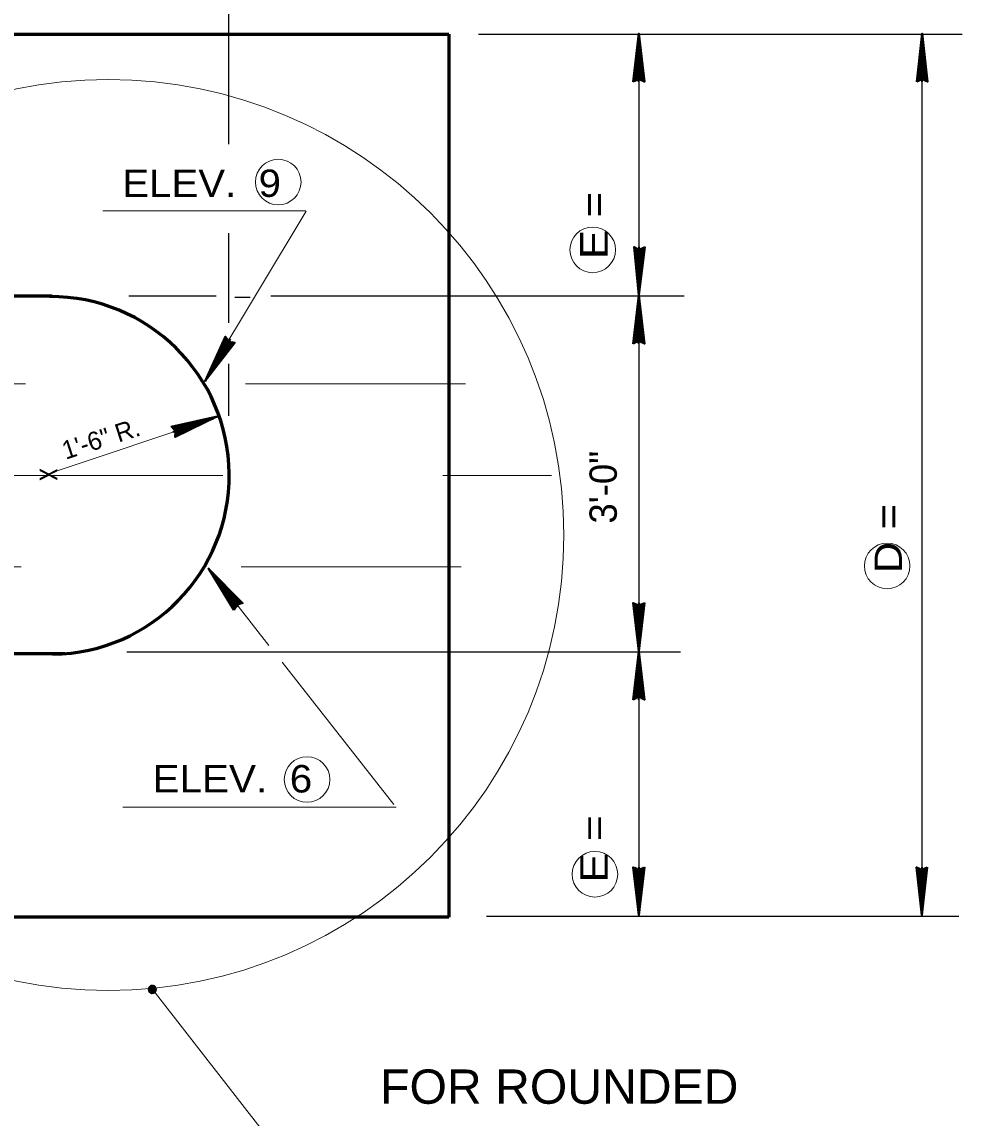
# Model space of a CAD drawing. Extents: x 1.6 to 19.9, y 2.8 to 9.5.
# Drawn here: x 17.2382 to 17.6655, y 8.7458 to 9.2441 of the extents above; entities that cross this region are included whole.
import ezdxf
from ezdxf.enums import TextEntityAlignment as Align

# ---------------------------------------------------------------- set-up
doc = ezdxf.new("R2010")
doc.units = 0
doc.header["$LTSCALE"] = 0.0047
doc.linetypes.add('DOT_DASHED', pattern=[7.7, 5, -1.2, 0.3, -1.2])
doc.layers.add('1', color=7, linetype='Continuous', lineweight=35)
doc.layers.add('5', color=7, linetype='Continuous', lineweight=13)

msp = doc.modelspace()

# ---------------------------------------------------------------- linework, layer by layer
at = {"layer": '1', "lineweight": 25}
for p, q in [((17.33225, 9.188583), (17.33225, 9.359333)), ((17.445667, 9.2385), (17.6655, 9.2385)), ((17.518583, 9.237417), (17.518583, 8.840083)), ((17.647167, 9.23825), (17.647167, 8.839)), ((17.33225, 9.107333), (17.33225, 9.148167)), ((17.28675, 9.119583), (17.3265, 9.119583)), ((17.334917, 9.119), (17.341917, 9.119)), ((17.351333, 9.119583), (17.53925, 9.119583)), ((17.33225, 9.065), (17.33225, 9.08875)), ((17.285917, 8.95775), (17.537583, 8.95775)), ((17.449333, 8.837667), (17.664083, 8.837667))]:
    msp.add_line(p, q, dxfattribs=at)
at = {"layer": '1'}
for p, q in [((17.518583, 9.216833), (17.518583, 9.238833)), ((17.647333, 9.216833), (17.647333, 9.238833)), ((17.516583, 9.21725), (17.51825, 9.233667)), ((17.516583, 9.21725), (17.518333, 9.233667)), ((17.51675, 9.21725), (17.518417, 9.233667)), ((17.645333, 9.21725), (17.647, 9.233667)), ((17.645333, 9.21725), (17.647083, 9.233667)), ((17.645333, 9.21725), (17.647167, 9.233667)), ((17.516833, 9.21725), (17.5185, 9.2335)), ((17.517, 9.21725), (17.51875, 9.2335)), ((17.519917, 9.217167), (17.518333, 9.232333)), ((17.52025, 9.21725), (17.518583, 9.232417)), ((17.520417, 9.21725), (17.51875, 9.2325)), ((17.520833, 9.21725), (17.519, 9.2325)), ((17.6455, 9.21725), (17.64725, 9.2335)), ((17.645667, 9.21725), (17.647417, 9.2335)), ((17.64875, 9.217167), (17.647083, 9.232333)), ((17.649083, 9.21725), (17.647333, 9.232417)), ((17.649333, 9.21725), (17.647667, 9.2325)), ((17.6495, 9.21725), (17.64775, 9.2325)), ((17.51675, 9.1415), (17.518333, 9.126083)), ((17.516917, 9.1415), (17.5185, 9.126083)), ((17.517167, 9.1415), (17.51875, 9.12625)), ((17.517417, 9.1415), (17.519, 9.12625)), ((17.518667, 9.141917), (17.518667, 9.119917)), ((17.520333, 9.1415), (17.518667, 9.125083)), ((17.52075, 9.1415), (17.51875, 9.125083)), ((17.521, 9.1415), (17.519, 9.125)), ((17.520917, 9.1415), (17.519, 9.125)), ((17.520833, 9.1415), (17.519, 9.125)), ((17.518583, 9.097833), (17.518583, 9.11975)), ((17.516583, 9.098333), (17.51825, 9.114667)), ((17.516583, 9.098167), (17.518333, 9.114667)), ((17.51675, 9.098167), (17.518417, 9.114667)), ((17.516833, 9.098167), (17.5185, 9.114583)), ((17.517, 9.098167), (17.51875, 9.114583)), ((17.519917, 9.098083), (17.518333, 9.113417)), ((17.52025, 9.098167), (17.518583, 9.1135)), ((17.520417, 9.098167), (17.51875, 9.113667)), ((17.520833, 9.098333), (17.519, 9.113667)), ((17.332917, 9.099917), (17.3215, 9.080833)), ((17.331, 9.100583), (17.324333, 9.086583)), ((17.331083, 9.1005), (17.324417, 9.086417)), ((17.33125, 9.100417), (17.324667, 9.086167)), ((17.3315, 9.100417), (17.325, 9.086167)), ((17.33425, 9.098667), (17.324, 9.085333)), ((17.334583, 9.098417), (17.324083, 9.085167)), ((17.334417, 9.0985), (17.32425, 9.085167)), ((17.334583, 9.098333), (17.324333, 9.085167)), ((17.334417, 9.098167), (17.324417, 9.085167)), ((17.30675, 9.057833), (17.32775, 9.065083)), ((17.306417, 9.059833), (17.323, 9.063333)), ((17.3065, 9.059833), (17.322833, 9.063333)), ((17.3065, 9.059583), (17.322833, 9.063333)), ((17.306667, 9.059833), (17.32275, 9.063583)), ((17.30675, 9.0595), (17.323, 9.06325)), ((17.30775, 9.056583), (17.321667, 9.063083)), ((17.307833, 9.056417), (17.322083, 9.063)), ((17.307833, 9.056333), (17.322, 9.06275)), ((17.308, 9.055833), (17.322, 9.062417)), ((17.336583, 8.97825), (17.323, 8.995667)), ((17.334667, 8.977167), (17.326, 8.991417)), ((17.334667, 8.977333), (17.326, 8.991333)), ((17.33475, 8.977167), (17.326083, 8.991583)), ((17.334917, 8.977333), (17.326083, 8.9915)), ((17.335083, 8.977417), (17.326333, 8.991667)), ((17.337583, 8.979417), (17.32675, 8.990417)), ((17.337667, 8.979667), (17.326833, 8.99075)), ((17.337833, 8.979833), (17.327083, 8.990917)), ((17.337917, 8.979833), (17.32725, 8.990917)), ((17.516583, 8.97975), (17.51825, 8.964417)), ((17.516833, 8.97975), (17.518417, 8.964417)), ((17.517083, 8.97975), (17.518667, 8.964417)), ((17.517333, 8.97975), (17.519, 8.9645)), ((17.518583, 8.980083), (17.518583, 8.958083)), ((17.520333, 8.97975), (17.518583, 8.963417)), ((17.520417, 8.97975), (17.518667, 8.963417)), ((17.52075, 8.97975), (17.518917, 8.963333)), ((17.520917, 8.97975), (17.519, 8.963333)), ((17.520833, 8.97975), (17.519, 8.963333)), ((17.518583, 8.936), (17.518583, 8.957917)), ((17.516583, 8.9365), (17.51825, 8.952833)), ((17.516583, 8.936333), (17.518333, 8.952833)), ((17.51675, 8.936333), (17.518417, 8.952833)), ((17.516833, 8.936333), (17.5185, 8.95275)), ((17.517, 8.936333), (17.51875, 8.95275)), ((17.519917, 8.93625), (17.518333, 8.951583)), ((17.52025, 8.936333), (17.518583, 8.951667)), ((17.520417, 8.936333), (17.51875, 8.95175)), ((17.520833, 8.9365), (17.519, 8.95175)), ((17.518583, 8.859917), (17.518583, 8.838)), ((17.647167, 8.859917), (17.647167, 8.838)), ((17.516583, 8.859583), (17.51825, 8.844333)), ((17.516833, 8.859583), (17.518417, 8.844333)), ((17.517083, 8.859583), (17.518667, 8.844417)), ((17.517333, 8.859583), (17.519, 8.8445)), ((17.520333, 8.859583), (17.518583, 8.843083)), ((17.520417, 8.859583), (17.518667, 8.843083)), ((17.52075, 8.859583), (17.518917, 8.843083)), ((17.520917, 8.859583), (17.519, 8.843083)), ((17.520833, 8.859583), (17.519, 8.843083)), ((17.645083, 8.859583), (17.646833, 8.844333)), ((17.645333, 8.859583), (17.647, 8.844333)), ((17.645583, 8.859583), (17.64725, 8.844417)), ((17.645833, 8.859583), (17.647667, 8.8445)), ((17.649, 8.859583), (17.647167, 8.843083)), ((17.649083, 8.859583), (17.64725, 8.843083)), ((17.649333, 8.859583), (17.647417, 8.843083)), ((17.649417, 8.859583), (17.647667, 8.843083)), ((17.649333, 8.859583), (17.647667, 8.843083))]:
    msp.add_line(p, q, dxfattribs=at)
at = {"layer": '1', "lineweight": 60}
for p, q in [((17.43225, 9.2385), (17.43225, 8.837167)), ((16.731, 9.119583), (17.252, 9.119583)), ((16.731, 8.957), (17.25775, 8.957)), ((17.43225, 8.837167), (16.629667, 8.837167))]:
    msp.add_line(p, q, dxfattribs=at)
at = {"layer": '1', "lineweight": 13}
for p, q in [((17.274917, 9.15825), (17.36725, 9.15825)), ((17.367417, 9.158167), (17.323583, 9.085167)), ((17.24925, 9.038417), (17.327667, 9.064583)), ((17.3505, 8.960667), (17.323583, 8.995)), ((17.407167, 8.888333), (17.356417, 8.953083)), ((17.284, 8.887167), (17.408333, 8.887167)), ((17.364083, 8.719), (17.29675, 8.805333))]:
    msp.add_line(p, q, dxfattribs=at)
at = {"layer": '1', "linetype": 'DOT_DASHED', "lineweight": 13}
for p, q in [((16.539833, 9.079667), (17.478917, 9.079667)), ((17.0295, 9.038), (17.478917, 9.038)), ((16.537917, 8.996417), (17.4745, 8.996417))]:
    msp.add_line(p, q, dxfattribs=at)
at = {"layer": '1', "lineweight": 40}
for p, q in [((17.296333, 8.805333), (17.29625, 8.803333)), ((17.2965, 8.805333), (17.296333, 8.803333)), ((17.296333, 8.805333), (17.29875, 8.80475)), ((17.296333, 8.805333), (17.29875, 8.804917)), ((17.296333, 8.805083), (17.29875, 8.804667)), ((17.2965, 8.805583), (17.29875, 8.805083)), ((17.296583, 8.805333), (17.2965, 8.803333)), ((17.296667, 8.805333), (17.296583, 8.803333)), ((17.29675, 8.805333), (17.296667, 8.803333)), ((17.297, 8.805333), (17.296917, 8.803333)), ((17.297083, 8.805333), (17.297, 8.803333)), ((17.297167, 8.805333), (17.297083, 8.803333)), ((17.29725, 8.805333), (17.297167, 8.803333)), ((17.297417, 8.805333), (17.29725, 8.803333)), ((17.2975, 8.805333), (17.297417, 8.803333)), ((17.297583, 8.805333), (17.2975, 8.803333)), ((17.29775, 8.805333), (17.297583, 8.80325)), ((17.298, 8.805333), (17.29775, 8.80325)), ((17.298083, 8.805333), (17.298, 8.80325)), ((17.298083, 8.805333), (17.298, 8.80325)), ((17.298167, 8.805333), (17.298083, 8.80325)), ((17.29825, 8.805333), (17.298167, 8.80325)), ((17.298417, 8.805333), (17.29825, 8.80325)), ((17.2985, 8.805333), (17.298417, 8.80325)), ((17.298667, 8.805333), (17.2985, 8.80325)), ((17.2985, 8.805333), (17.2985, 8.80325)), ((17.298833, 8.805333), (17.29875, 8.80325)), ((17.296167, 8.8035), (17.2985, 8.803083)), ((17.29625, 8.80475), (17.298667, 8.80425)), ((17.29625, 8.804667), (17.298667, 8.804)), ((17.29625, 8.804417), (17.2985, 8.803833)), ((17.29625, 8.804333), (17.2985, 8.803833)), ((17.29625, 8.804083), (17.2985, 8.803583)), ((17.29625, 8.803833), (17.2985, 8.803333)), ((17.29625, 8.803583), (17.2985, 8.803167)), ((17.29625, 8.803583), (17.2985, 8.80325)), ((17.296333, 8.805), (17.29875, 8.804417)), ((17.296333, 8.80475), (17.298667, 8.804333))]:
    msp.add_line(p, q, dxfattribs=at)
at = {"layer": '1'}
for points in [[(17.516083, 9.216833), (17.518583, 9.238833), (17.521167, 9.216833), (17.518583, 9.218)], [(17.645, 9.216833), (17.647333, 9.238833), (17.649833, 9.216833), (17.647333, 9.218)], [(17.52125, 9.141917), (17.518667, 9.119917), (17.516417, 9.141917), (17.51875, 9.140667)], [(17.519, 9.140333), (17.519333, 9.134), (17.519333, 9.140667), (17.5195, 9.136083), (17.51975, 9.140833), (17.51925, 9.133333), (17.51875, 9.123583), (17.518333, 9.125667), (17.518583, 9.122917), (17.5185, 9.140333), (17.518167, 9.13525), (17.518167, 9.140667), (17.519, 9.129417), (17.51775, 9.140833)], [(17.519, 9.140333), (17.519, 9.130583), (17.51875, 9.130667), (17.519, 9.1325)], [(17.516083, 9.097833), (17.518583, 9.11975), (17.521167, 9.097833), (17.518583, 9.099)], [(17.335167, 9.098417), (17.3215, 9.080833), (17.33075, 9.101083), (17.33225, 9.098833)], [(17.33225, 9.098333), (17.327417, 9.089833), (17.32725, 9.09), (17.32825, 9.091667), (17.332583, 9.098333), (17.329333, 9.092583), (17.332917, 9.098333), (17.330667, 9.094417), (17.333417, 9.098417), (17.329, 9.092167), (17.3235, 9.084), (17.324, 9.085917), (17.322833, 9.083583), (17.332, 9.0985), (17.329083, 9.094417), (17.331917, 9.099), (17.32675, 9.089083), (17.331583, 9.099417)], [(17.306083, 9.060167), (17.32775, 9.065083), (17.307833, 9.055333), (17.308, 9.058083)], [(17.334583, 8.976667), (17.323, 8.995667), (17.338583, 8.979833), (17.336, 8.979167)], [(17.521167, 8.980083), (17.518583, 8.958083), (17.516083, 8.980083), (17.518667, 8.979)], [(17.519, 8.978667), (17.519, 8.968833), (17.51875, 8.968917), (17.519, 8.97075)], [(17.516083, 8.936), (17.518583, 8.957917), (17.521167, 8.936), (17.518583, 8.93725)], [(17.521167, 8.859917), (17.518583, 8.838), (17.516083, 8.859917), (17.518667, 8.858833)], [(17.649667, 8.859917), (17.647167, 8.838), (17.644833, 8.859917), (17.64725, 8.858833)], [(17.519, 8.8585), (17.519, 8.848833), (17.51875, 8.848833), (17.519, 8.850583)], [(17.647667, 8.8585), (17.647667, 8.848833), (17.647333, 8.848833), (17.647667, 8.850583)]]:
    msp.add_lwpolyline(points, close=True, dxfattribs=at)
at = {"layer": '1', "lineweight": 60}
msp.add_lwpolyline([(16.629667, 8.837167), (16.629667, 9.2385), (17.43225, 9.2385)], dxfattribs=at)
at = {"layer": '1'}
for points in [[(17.518333, 9.218333), (17.518167, 9.228083), (17.5185, 9.228), (17.518333, 9.22625), (17.518167, 9.218333), (17.518, 9.224583), (17.517833, 9.218083), (17.51775, 9.222583), (17.5175, 9.217833), (17.518, 9.225417), (17.5185, 9.235167), (17.519, 9.233083), (17.51875, 9.235833), (17.51875, 9.218333), (17.519083, 9.223417), (17.519083, 9.218083), (17.518417, 9.229167), (17.5195, 9.217917), (17.518417, 9.218417), (17.516917, 9.217417), (17.51725, 9.217917), (17.518, 9.218417), (17.517833, 9.218833), (17.517167, 9.218583), (17.518667, 9.21825), (17.5195, 9.217833), (17.52075, 9.21725)], [(17.647083, 9.218333), (17.646917, 9.228083), (17.64725, 9.228), (17.647083, 9.22625), (17.646917, 9.218333), (17.64675, 9.224583), (17.646667, 9.218083), (17.6465, 9.222583), (17.646333, 9.217833), (17.64675, 9.225417), (17.64725, 9.235167), (17.64775, 9.233083), (17.647417, 9.235833), (17.647667, 9.218333), (17.648, 9.223417), (17.648, 9.218083), (17.647167, 9.229167), (17.648333, 9.217917), (17.647167, 9.218417), (17.645583, 9.217417), (17.645917, 9.217917), (17.64675, 9.218417), (17.646667, 9.218833), (17.645833, 9.218583), (17.647417, 9.21825), (17.648333, 9.217833), (17.649417, 9.21725)], [(17.519, 9.140333), (17.520417, 9.141333), (17.520083, 9.140833), (17.51925, 9.140333), (17.519417, 9.13975), (17.52025, 9.140167), (17.518667, 9.1405), (17.51775, 9.140917), (17.51675, 9.1415)], [(17.518333, 9.099333), (17.518167, 9.109083), (17.5185, 9.109), (17.518333, 9.107167), (17.518167, 9.099333), (17.518, 9.105667), (17.517833, 9.099083), (17.51775, 9.103667), (17.5175, 9.098833), (17.518, 9.106333), (17.5185, 9.116167), (17.519, 9.114083), (17.51875, 9.11675), (17.51875, 9.099333), (17.519083, 9.1045), (17.519083, 9.099083), (17.518417, 9.110333), (17.5195, 9.098917), (17.518417, 9.099417), (17.516917, 9.098333), (17.51725, 9.098917), (17.518, 9.099417), (17.517833, 9.099917), (17.517167, 9.099583), (17.518667, 9.099167), (17.5195, 9.098833), (17.52075, 9.098333)], [(17.33225, 9.098333), (17.33425, 9.098333), (17.333583, 9.098083), (17.332667, 9.098083), (17.3325, 9.097583), (17.333333, 9.097583), (17.332083, 9.09875), (17.331583, 9.099583), (17.330833, 9.1005)], [(17.308417, 9.058417), (17.317583, 9.061917), (17.31775, 9.06175), (17.315583, 9.061333), (17.308083, 9.05875), (17.31425, 9.061083), (17.307667, 9.058833), (17.312083, 9.060583), (17.307167, 9.059167), (17.31475, 9.061333), (17.32425, 9.063833), (17.3225, 9.06275), (17.325083, 9.063833), (17.308417, 9.058083), (17.31325, 9.0595), (17.30825, 9.057833), (17.3185, 9.062083), (17.308083, 9.057333), (17.308417, 9.058333), (17.30675, 9.059667), (17.307417, 9.059333), (17.308083, 9.058917), (17.30875, 9.05925), (17.308083, 9.059667), (17.308083, 9.058083), (17.308, 9.057167), (17.308083, 9.056167)], [(17.3355, 8.97925), (17.329333, 8.987), (17.329583, 8.987), (17.330667, 8.985417), (17.335417, 8.979), (17.331167, 8.984083), (17.335333, 8.97875), (17.33225, 8.982333), (17.33525, 8.97825), (17.330833, 8.984667), (17.325083, 8.99275), (17.326833, 8.9915), (17.324917, 8.993417), (17.33575, 8.979667), (17.332833, 8.98375), (17.33625, 8.979417), (17.328833, 8.987917), (17.33675, 8.979667), (17.335583, 8.979333), (17.334917, 8.9775), (17.33475, 8.97825), (17.335167, 8.979), (17.334667, 8.979333), (17.334417, 8.978667), (17.335917, 8.979333), (17.336833, 8.979667), (17.337833, 8.98)], [(17.519, 8.978667), (17.51925, 8.972417), (17.51925, 8.979), (17.519417, 8.974333), (17.519667, 8.979083), (17.51925, 8.971583), (17.51875, 8.96175), (17.51825, 8.963917), (17.5185, 8.961167), (17.518417, 8.978667), (17.518083, 8.9735), (17.518083, 8.979), (17.518917, 8.96775), (17.517667, 8.979), (17.518917, 8.9785), (17.520333, 8.9795), (17.520083, 8.979), (17.51925, 8.9785), (17.519333, 8.978), (17.520083, 8.978417), (17.518583, 8.97875), (17.517667, 8.979167), (17.51675, 8.97975)], [(17.518333, 8.937583), (17.518167, 8.94725), (17.5185, 8.947167), (17.518333, 8.94525), (17.518167, 8.937583), (17.518, 8.943833), (17.517833, 8.937333), (17.51775, 8.941917), (17.5175, 8.937083), (17.518, 8.9445), (17.5185, 8.954417), (17.519, 8.95225), (17.51875, 8.955), (17.51875, 8.937583), (17.519083, 8.942667), (17.519083, 8.937333), (17.518417, 8.9485), (17.5195, 8.937167), (17.518417, 8.937667), (17.516917, 8.9365), (17.51725, 8.937167), (17.518, 8.937667), (17.517833, 8.938083), (17.517167, 8.93775), (17.518667, 8.937417), (17.5195, 8.937083), (17.52075, 8.9365)], [(17.519, 8.8585), (17.51925, 8.852167), (17.51925, 8.858833), (17.519417, 8.854167), (17.519667, 8.859), (17.51925, 8.851333), (17.51875, 8.841667), (17.51825, 8.84375), (17.5185, 8.841083), (17.518417, 8.8585), (17.518083, 8.8535), (17.518083, 8.858833), (17.518917, 8.847417), (17.517667, 8.858917), (17.518917, 8.858417), (17.520333, 8.859333), (17.520083, 8.858917), (17.51925, 8.858417), (17.519333, 8.858), (17.520083, 8.858333), (17.518583, 8.858583), (17.517667, 8.859083), (17.51675, 8.859583)], [(17.647667, 8.8585), (17.648, 8.852167), (17.648, 8.858833), (17.648083, 8.854167), (17.648333, 8.859), (17.647833, 8.851333), (17.647333, 8.841667), (17.646833, 8.84375), (17.647083, 8.841083), (17.647, 8.8585), (17.646667, 8.8535), (17.646667, 8.858833), (17.647417, 8.847417), (17.646083, 8.858917), (17.647417, 8.858417), (17.649083, 8.859333), (17.648667, 8.858917), (17.647833, 8.858417), (17.648, 8.858), (17.64875, 8.858333), (17.647167, 8.858583), (17.646083, 8.859083), (17.645167, 8.859583)]]:
    msp.add_lwpolyline(points, dxfattribs=at)
at = {"layer": '1', "lineweight": 40}
msp.add_lwpolyline([(17.295917, 8.80425), (17.299, 8.80475), (17.29625, 8.805333), (17.299, 8.803833), (17.296167, 8.803333), (17.2985, 8.803), (17.2985, 8.805667), (17.297417, 8.802667), (17.29775, 8.806), (17.2965, 8.803), (17.296917, 8.806), (17.297833, 8.802667), (17.296, 8.804917), (17.298833, 8.805083), (17.296917, 8.80275), (17.298167, 8.805917), (17.29625, 8.805333), (17.296167, 8.803333), (17.297417, 8.802667), (17.2985, 8.803), (17.299, 8.803833), (17.298833, 8.805083), (17.298167, 8.805917), (17.297417, 8.804417), (17.29875, 8.80325), (17.2965, 8.803), (17.297417, 8.804417), (17.296167, 8.805083), (17.29725, 8.806), (17.297417, 8.804667), (17.298417, 8.803), (17.296, 8.804667), (17.297583, 8.805), (17.2985, 8.805667)], dxfattribs=at)
at = {"layer": '1', "lineweight": 13}
for centre, radius in [((17.277479, 9.010857), 0.207058), ((17.354707, 9.171344), 0.010363), ((17.497638, 9.140502), 0.010363), ((17.63145, 8.996825), 0.010363), ((17.367806, 8.899741), 0.010363), ((17.498633, 8.856629), 0.010363)]:
    msp.add_circle(centre, radius, dxfattribs=at)
at = {"layer": '1', "lineweight": 40}
msp.add_circle((17.29748, 8.804294), 0.001641, dxfattribs=at)
at = {"layer": '1', "lineweight": 60}
msp.add_arc((17.251114, 9.037967), 0.081332, 270.82013, 90.23291, dxfattribs=at)

# ---------------------------------------------------------------- texts
at = {"layer": '1'}
for s, height, rotation, p in [('1\'-6" R.', 0.008333, 17.925, (17.258083, 9.045083)), ('3\'-0"', 0.01242, 90, (17.508583, 9.016083))]:
    msp.add_text(s, height=height, rotation=rotation, dxfattribs=at).set_placement(p)
at = {"layer": '1', "width": 0.8}
msp.add_text('x', height=0.01042, rotation=270, dxfattribs=at).set_placement((17.246333, 9.038333), align=Align.CENTER)
at = {"layer": '5'}
for s, height, width, p in [('ELEV.  9', 0.01242, 1.1, (17.283833, 9.164583)), ('ELEV.  6', 0.0125, 1.1, (17.297583, 8.893833)), ('FOR ROUNDED', 0.01558, 1.05, (17.401, 8.752333))]:
    msp.add_text(s, height=height, dxfattribs=dict(at, width=width)).set_placement(p)
at = {"layer": '5', "width": 1.2}
for s, height, p in [('E =      ', 0.0125, (17.504417, 9.13625)), ('D =      ', 0.01242, (17.638167, 8.993417)), ('E =      ', 0.0125, (17.5045, 8.852833))]:
    msp.add_text(s, height=height, rotation=90, dxfattribs=at).set_placement(p)

doc.saveas('drawing.dxf')
